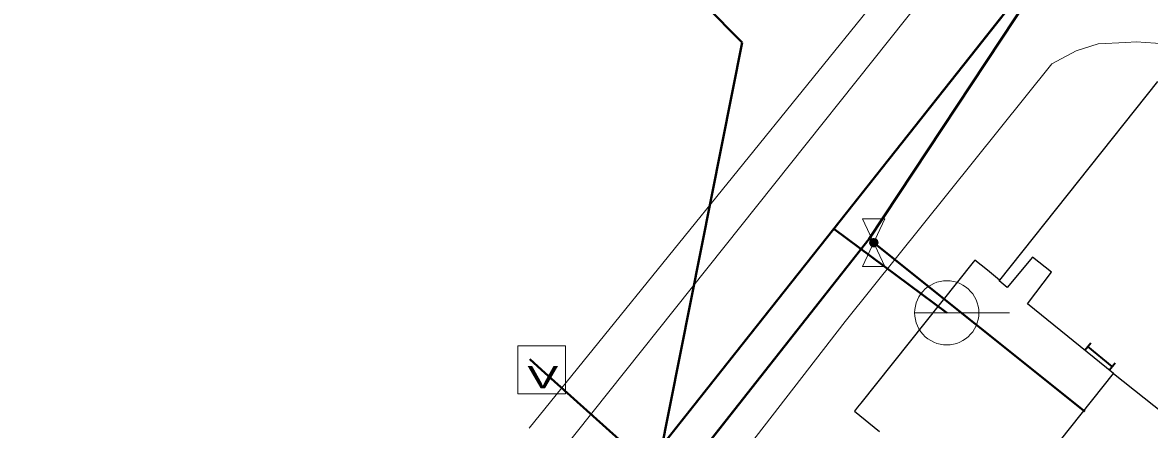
# Model space of a CAD drawing. Extents: x -968691 to -140888, y -1376050 to -879856.
# Drawn here: x -646150.94 to -646115.56, y -1062511.09 to -1062498.32 of the extents above; entities that cross this region are included whole.
import ezdxf
from ezdxf.enums import TextEntityAlignment as Align

# ---------------------------------------------------------------- set-up
doc = ezdxf.new("R2010")
doc.units = 0
doc.header["$LTSCALE"] = 4.8
for name, pattern in [('DASH_DOUBLE_DOT', [9.2, 5, -1.2, 0.3, -1.2, 0.3, -1.2]), ('DOTTED', [1.5, 0.3, -1.2]), ('LONG_DASHED', [7.5, 6, -1.5]), ('MEDIUM_DASHED', [4.5, 3, -1.5])]:
    doc.linetypes.add(name, pattern=pattern)
doc.layers.add('1', color=7, linetype='Continuous', lineweight=13)

msp = doc.modelspace()

# ---------------------------------------------------------------- hatches: boundary and pattern name
at = {"layer": '1'}
msp.add_hatch(color=256, dxfattribs=at).paths.add_polyline_path([(-646124.078, -1062505.23), (-646124.08, -1062505.206), (-646124.087, -1062505.183), (-646124.097, -1062505.161), (-646124.111, -1062505.142), (-646124.129, -1062505.125), (-646124.149, -1062505.112), (-646124.172, -1062505.103), (-646124.195, -1062505.099), (-646124.219, -1062505.098), (-646124.243, -1062505.102), (-646124.266, -1062505.11), (-646124.287, -1062505.122), (-646124.305, -1062505.138), (-646124.32, -1062505.157), (-646124.332, -1062505.178), (-646124.339, -1062505.201), (-646124.342, -1062505.225), (-646124.341, -1062505.249), (-646124.335, -1062505.272), (-646124.325, -1062505.294), (-646124.312, -1062505.314), (-646124.295, -1062505.331), (-646124.275, -1062505.345), (-646124.253, -1062505.355), (-646124.23, -1062505.361), (-646124.206, -1062505.362), (-646124.182, -1062505.359), (-646124.159, -1062505.352), (-646124.138, -1062505.341), (-646124.119, -1062505.326), (-646124.103, -1062505.307), (-646124.091, -1062505.287), (-646124.082, -1062505.264), (-646124.078, -1062505.24)])

# ---------------------------------------------------------------- linework, layer by layer
at = {"layer": '1', "linetype": 'DASH_DOUBLE_DOT', "lineweight": 40}
for p in [(-646160.49, -1062466.29), (-646149.08, -1062603.085)]:
    msp.add_line(p, (-646128.34, -1062498.95), dxfattribs=at)
at = {"layer": '1', "linetype": 'LONG_DASHED', "lineweight": 40}
for p, q in [((-646116.93, -1062493.87), (-646124.36, -1062505.11)), ((-646125.463, -1062504.79), (-646117.57, -1062494.82)), ((-646121.92, -1062507.43), (-646125.463, -1062504.79)), ((-646124.36, -1062505.11), (-646130.5, -1062512.9)), ((-646124.36, -1062505.11), (-646124.21, -1062505.23)), ((-646124.21, -1062505.23), (-646117.58, -1062510.532)), ((-646134.64, -1062509.22), (-646130.63, -1062512.81))]:
    msp.add_line(p, q, dxfattribs=at)
at = {"layer": '1', "lineweight": 35}
for p, q in [((-646116.93, -1062493.87), (-646124.36, -1062505.11)), ((-646125.463, -1062504.79), (-646117.57, -1062494.82)), ((-646124.36, -1062505.11), (-646130.5, -1062512.9)), ((-646117.58, -1062508.6), (-646117.397, -1062508.374)), ((-646116.722, -1062509.111), (-646117.491, -1062508.49)), ((-646116.81, -1062509.22), (-646116.629, -1062508.995))]:
    msp.add_line(p, q, dxfattribs=at)
at = {"layer": '1'}
for p, q in [((-646121.569, -1062494.426), (-646135.034, -1062511.051)), ((-646135.09, -1062513.113), (-646120.7, -1062495.06)), ((-646125.112, -1062507.701), (-646118.62, -1062499.61)), ((-646121.92, -1062507.43), (-646125.463, -1062504.79)), ((-646124.36, -1062505.11), (-646124.21, -1062505.23)), ((-646124.21, -1062505.23), (-646117.58, -1062510.532)), ((-646128.903, -1062512.606), (-646125.112, -1062507.701)), ((-646122.928, -1062507.43), (-646119.952, -1062507.43)), ((-646134.64, -1062509.22), (-646135.013, -1062508.886)), ((-646134.64, -1062509.22), (-646130.63, -1062512.81))]:
    msp.add_line(p, q, dxfattribs=at)
at = {"layer": '1', "lineweight": 25}
for p, q in [((-646115.3, -1062500.17), (-646120.26, -1062506.41)), ((-646120.27, -1062506.43), (-646120.26, -1062506.41)), ((-646116.69, -1062509.33), (-646119.39, -1062507.15))]:
    msp.add_line(p, q, dxfattribs=at)
at = {"layer": '1', "linetype": 'MEDIUM_DASHED', "lineweight": 25}
for p, q in [((-646121.091, -1062505.844), (-646124.613, -1062510.261)), ((-646121.04, -1062505.78), (-646121.091, -1062505.844)), ((-646120.643, -1062506.096), (-646121.04, -1062505.78)), ((-646120.26, -1062506.41), (-646120.643, -1062506.096)), ((-646116.69, -1062509.33), (-646112.43, -1062512.72))]:
    msp.add_line(p, q, dxfattribs=at)
at = {"layer": '1', "linetype": 'DOTTED', "lineweight": 40}
msp.add_line((-646134.64, -1062509.22), (-646135.013, -1062508.886), dxfattribs=at)
at = {"layer": '1'}
msp.add_lwpolyline([(-646118.62, -1062499.61), (-646117.853, -1062499.202), (-646117.17, -1062498.99), (-646116.298, -1062498.943), (-646115.974, -1062498.926), (-646115.059, -1062498.989), (-646114.42, -1062499.13)], dxfattribs=at)
for points in [[(-646124.56, -1062504.48), (-646123.86, -1062504.48), (-646124.56, -1062505.98), (-646123.86, -1062505.98)], [(-646124.078, -1062505.23), (-646124.08, -1062505.206), (-646124.087, -1062505.183), (-646124.097, -1062505.161), (-646124.111, -1062505.142), (-646124.129, -1062505.125), (-646124.149, -1062505.112), (-646124.172, -1062505.103), (-646124.195, -1062505.099), (-646124.219, -1062505.098), (-646124.243, -1062505.102), (-646124.266, -1062505.11), (-646124.287, -1062505.122), (-646124.305, -1062505.138), (-646124.32, -1062505.157), (-646124.332, -1062505.178), (-646124.339, -1062505.201), (-646124.342, -1062505.225), (-646124.341, -1062505.249), (-646124.335, -1062505.272), (-646124.325, -1062505.294), (-646124.312, -1062505.314), (-646124.295, -1062505.331), (-646124.275, -1062505.345), (-646124.253, -1062505.355), (-646124.23, -1062505.361), (-646124.206, -1062505.362), (-646124.182, -1062505.359), (-646124.159, -1062505.352), (-646124.138, -1062505.341), (-646124.119, -1062505.326), (-646124.103, -1062505.307), (-646124.091, -1062505.287), (-646124.082, -1062505.264), (-646124.078, -1062505.24)], [(-646121.92, -1062506.422), (-646122.025, -1062506.428), (-646122.129, -1062506.444), (-646122.231, -1062506.472), (-646122.33, -1062506.51), (-646122.424, -1062506.557), (-646122.512, -1062506.615), (-646122.594, -1062506.681), (-646122.669, -1062506.756), (-646122.735, -1062506.838), (-646122.793, -1062506.926), (-646122.84, -1062507.02), (-646122.878, -1062507.119), (-646122.906, -1062507.221), (-646122.922, -1062507.325), (-646122.928, -1062507.43), (-646122.922, -1062507.535), (-646122.906, -1062507.64), (-646122.878, -1062507.742), (-646122.84, -1062507.84), (-646122.793, -1062507.934), (-646122.735, -1062508.023), (-646122.669, -1062508.105), (-646122.594, -1062508.179), (-646122.512, -1062508.245), (-646122.424, -1062508.303), (-646122.33, -1062508.351), (-646122.231, -1062508.389), (-646122.129, -1062508.416), (-646122.025, -1062508.432), (-646121.92, -1062508.438), (-646121.815, -1062508.432), (-646121.71, -1062508.416), (-646121.608, -1062508.389), (-646121.51, -1062508.351), (-646121.416, -1062508.303), (-646121.327, -1062508.245), (-646121.245, -1062508.179), (-646121.171, -1062508.105), (-646121.105, -1062508.023), (-646121.047, -1062507.934), (-646120.999, -1062507.84), (-646120.961, -1062507.742), (-646120.934, -1062507.64), (-646120.918, -1062507.535), (-646120.912, -1062507.43), (-646120.918, -1062507.325), (-646120.934, -1062507.221), (-646120.961, -1062507.119), (-646120.999, -1062507.02), (-646121.047, -1062506.926), (-646121.105, -1062506.838), (-646121.171, -1062506.756), (-646121.245, -1062506.681), (-646121.327, -1062506.615), (-646121.416, -1062506.557), (-646121.51, -1062506.51), (-646121.608, -1062506.472), (-646121.71, -1062506.444), (-646121.815, -1062506.428)], [(-646135.39, -1062509.97), (-646133.89, -1062509.97), (-646133.89, -1062508.47), (-646135.39, -1062508.47)]]:
    msp.add_lwpolyline(points, close=True, dxfattribs=at)
at = {"layer": '1', "linetype": 'LONG_DASHED', "lineweight": 40}
msp.add_lwpolyline([(-646125.463, -1062504.79), (-646134.145, -1062515.74), (-646136.081, -1062518.202), (-646142.83, -1062526.728), (-646149.07, -1062534.61)], dxfattribs=at)
at = {"layer": '1', "lineweight": 35}
msp.add_lwpolyline([(-646125.463, -1062504.79), (-646134.145, -1062515.74), (-646136.081, -1062518.202), (-646142.83, -1062526.728), (-646149.07, -1062534.61)], dxfattribs=at)
at = {"layer": '1', "lineweight": 25}
for points in [[(-646119.39, -1062507.15), (-646118.63, -1062506.15), (-646119.23, -1062505.68), (-646120.02, -1062506.63), (-646120.27, -1062506.43)], [(-646116.13, -1062517.35), (-646120.38, -1062513.98), (-646116.69, -1062509.33)]]:
    msp.add_lwpolyline(points, dxfattribs=at)
at = {"layer": '1', "linetype": 'MEDIUM_DASHED', "lineweight": 25}
msp.add_lwpolyline([(-646124.613, -1062510.261), (-646124.719, -1062510.394), (-646124.82, -1062510.52), (-646124.033, -1062511.151)], dxfattribs=at)

# ---------------------------------------------------------------- texts
at = {"layer": '1', "width": 1.55}
msp.add_text('V', height=0.7, dxfattribs=at).set_placement((-646134.601, -1062509.799), align=Align.CENTER)

doc.saveas('drawing.dxf')
